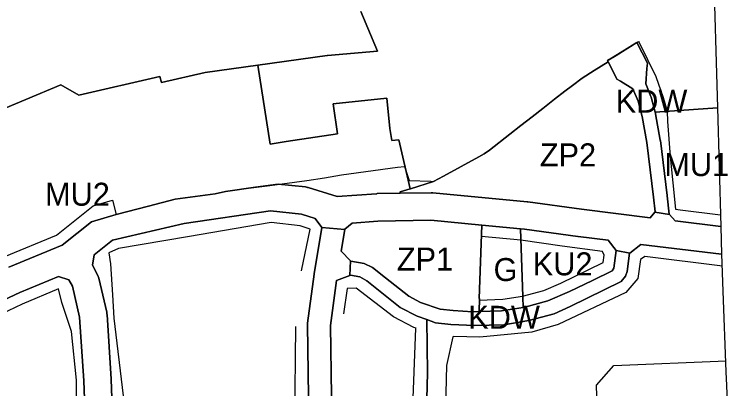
# Model space of a CAD drawing. Extents: x 7425930 to 7427318, y 5544765 to 5546387.
# Drawn here: x 7426835.8 to 7427147, y 5545888.3 to 5546051.3 of the extents above; entities that cross this region are included whole.
import ezdxf

# ---------------------------------------------------------------- set-up
doc = ezdxf.new("R2010")
doc.units = 0
for name, color, linetype in [('linie_rozgraniczajace', 7, 'Continuous'), ('linie_zabudowy_nieprzekraczalne', 7, 'Continuous'), ('oznaczenia_przeznaczen', 7, 'Continuous')]:
    doc.layers.add(name, color=color, linetype=linetype)

msp = doc.modelspace()

# ---------------------------------------------------------------- linework, layer by layer
at = {"layer": 'linie_rozgraniczajace'}
for points in [[(7427140.18, 5546075.21), (7427142.05, 5546010.56), (7427114.98, 5546008.71), (7427113.23, 5546015.19), (7427113.13, 5546015.48), (7427113.12, 5546015.54), (7427110.85, 5546021.1), (7427111.38, 5546027.77), (7427111.56, 5546030.07), (7427107.01, 5546038.98), (7427096.61, 5546032.62), (7427094.25, 5546031.18), (7427094.51, 5546030.67), (7427094.49, 5546030.68), (7427088.36, 5546026.88), (7427083.22, 5546023.55), (7427079.01, 5546020.35), (7427075.69, 5546017.81), (7427071.18, 5546014.31), (7427066.03, 5546010.32), (7427061.37, 5546006.7), (7427056.45, 5546002.89), (7427051.71, 5545999.17), (7427042.82, 5545992.23), (7427040.55, 5545990.61), (7427038.16, 5545989.19), (7427022.76, 5545980.8), (7427018.48, 5545978.47), (7427008.34, 5545975.33), (7427008.24, 5545975.37), (7427003.31, 5545996.73), (7427000.28, 5545996.34), (7426999.47, 5546001.6), (7426998.11, 5546014.82), (7426974.71, 5546012.35), (7426976.63, 5545999.33), (7426954.2, 5545995.96), (7426947.33, 5545994.79), (7426941.89, 5546029.19), (7426972.15, 5546033.4), (7426972.24, 5546033.33), (7426994.07, 5546035.21), (7426986.79, 5546052.49)], [(7426986.79, 5546052.49), (7426994.07, 5546035.21), (7426972.24, 5546033.33), (7426972.15, 5546033.4), (7426941.89, 5546029.19), (7426919.02, 5546026.02), (7426900, 5546021.67), (7426899.24, 5546024.29), (7426863.95, 5546016.1), (7426856.16, 5546020.62), (7426825.43, 5546007.85)], [(7426825.43, 5546007.85), (7426856.16, 5546020.62), (7426863.95, 5546016.1), (7426899.24, 5546024.29), (7426900, 5546021.67), (7426919.02, 5546026.02), (7426941.89, 5546029.19), (7426947.33, 5545994.79), (7426954.2, 5545995.96), (7426976.63, 5545999.33), (7426974.71, 5546012.35), (7426998.11, 5546014.82), (7426999.47, 5546001.6), (7427000.28, 5545996.34), (7427003.31, 5545996.73), (7427008.24, 5545975.37), (7427008.25, 5545975.32), (7427003.87, 5545974.01), (7427003.93, 5545973.41), (7426993.85, 5545973.23), (7426993.7, 5545973.19), (7426993.54, 5545973.21), (7426976.44, 5545972.02), (7426963.83, 5545975.91), (7426963.53, 5545975.95), (7426962.7, 5545976.14), (7426950.76, 5545977.41), (7426940.96, 5545976.11), (7426927.84, 5545974.14), (7426923.32, 5545973.18), (7426905.94, 5545970.85), (7426894.3, 5545967.8), (7426880.15, 5545964.12), (7426869.47, 5545960.98), (7426856.72, 5545950.85), (7426833.54, 5545941.2)], [(7426833.54, 5545941.2), (7426856.72, 5545950.85), (7426869.47, 5545960.98), (7426880.15, 5545964.12), (7426894.3, 5545967.8), (7426905.94, 5545970.85), (7426923.32, 5545973.18), (7426927.84, 5545974.14), (7426940.96, 5545976.11), (7426950.76, 5545977.41), (7426962.7, 5545976.14), (7426963.53, 5545975.95), (7426963.83, 5545975.91), (7426976.44, 5545972.02), (7426993.54, 5545973.21), (7426993.7, 5545973.19), (7426993.85, 5545973.23), (7427003.93, 5545973.41), (7427017.4, 5545973.65), (7427017.46, 5545973.65), (7427018.07, 5545973.63), (7427059.27, 5545969.74), (7427059.38, 5545969.72), (7427059.54, 5545969.71), (7427082.93, 5545966.43), (7427112.84, 5545962.74), (7427114.85, 5545965.17), (7427121.24, 5545964.14), (7427123.64, 5545961.4), (7427143.54, 5545958.95), (7427143.89, 5545946.81), (7427108.72, 5545951.16), (7427103.92, 5545947.35), (7427097.94, 5545948.41), (7427097.95, 5545948.51), (7427094.53, 5545952.91), (7427081.41, 5545954.53), (7427081.37, 5545954.54), (7427081.31, 5545954.54), (7427058.01, 5545957.81), (7427056.26, 5545957.97), (7427039.48, 5545959.56), (7427017.28, 5545961.65), (7426994.22, 5545961.23), (7426982.96, 5545960.45), (7426979.78, 5545957.8), (7426979.74, 5545957.6), (7426969.75, 5545958.56), (7426966.83, 5545962.43), (7426960.86, 5545964.27), (7426947.44, 5545965.69), (7426909.86, 5545960.25), (7426878.64, 5545952.93), (7426870.65, 5545946.59), (7426869.88, 5545942.05), (7426872.1, 5545937.95), (7426872.14, 5545937.78), (7426872.26, 5545937.62)], [(7426878.81, 5545872.44), (7426878.06, 5545892.28), (7426878.04, 5545892.36), (7426878.05, 5545892.43), (7426876.24, 5545920.67), (7426876.22, 5545920.76), (7426876.1, 5545921.64), (7426872.66, 5545936.46), (7426872.26, 5545937.62), (7426872.14, 5545937.78), (7426872.1, 5545937.95), (7426869.88, 5545942.05), (7426870.65, 5545946.59), (7426878.64, 5545952.93), (7426909.86, 5545960.25), (7426947.44, 5545965.69), (7426960.86, 5545964.27), (7426966.83, 5545962.43), (7426969.75, 5545958.56), (7426969.76, 5545958.55), (7426966.41, 5545938.27), (7426966.4, 5545938.18), (7426966.38, 5545938.11), (7426963.54, 5545916.81), (7426963.51, 5545916.15), (7426963.5, 5545916.08), (7426963.97, 5545884.9)], [(7426963.97, 5545884.9), (7426963.5, 5545916.08), (7426963.51, 5545916.15), (7426963.54, 5545916.81), (7426966.38, 5545938.11), (7426966.4, 5545938.18), (7426966.41, 5545938.27), (7426969.76, 5545958.55), (7426969.75, 5545958.56), (7426979.74, 5545957.6), (7426978.19, 5545948.25), (7426982.33, 5545943.95), (7426981.95, 5545937.55), (7426976.11, 5545935.38), (7426973.5, 5545915.86), (7426973.97, 5545885)], [(7427013.96, 5545822.16), (7427015.76, 5545895.24), (7427015.45, 5545918.38), (7427019.32, 5545917.02), (7427025.9, 5545916.29), (7427036.25, 5545915.79), (7427049.07, 5545916.17), (7427059.99, 5545917.94), (7427070.99, 5545920.9), (7427077.88, 5545924.1), (7427100.08, 5545934.93), (7427102.1, 5545937.26), (7427102.81, 5545939.27), (7427103.79, 5545947.25), (7427103.92, 5545947.35), (7427108.72, 5545951.16), (7427143.89, 5545946.81), (7427144.36, 5545930.79), (7427145.78, 5545895.67), (7427145.78, 5545895.64), (7427146.03, 5545889.65), (7427146.03, 5545889.57), (7427146.99, 5545865.9)], [(7426821.46, 5545922.33), (7426838.26, 5545930.17), (7426855.15, 5545937.2), (7426859.65, 5545935.74), (7426861.15, 5545932.96), (7426864.3, 5545919.41), (7426866.07, 5545891.75), (7426866.82, 5545871.96), (7426866.82, 5545871.93), (7426866.82, 5545871.9), (7426868.4, 5545838.29), (7426859.6, 5545808.92), (7426847.88, 5545776.09), (7426847.88, 5545776.07), (7426847.87, 5545776.06), (7426842.94, 5545761.99), (7426840.91, 5545750.25), (7426829.1, 5545718.41)], [(7426829.1, 5545718.41), (7426840.91, 5545750.25), (7426842.94, 5545761.99), (7426847.87, 5545776.06), (7426847.88, 5545776.07), (7426847.88, 5545776.09), (7426859.6, 5545808.92), (7426868.4, 5545838.29), (7426866.82, 5545871.9), (7426866.82, 5545871.93), (7426866.82, 5545871.96), (7426866.07, 5545891.75), (7426864.3, 5545919.41), (7426861.15, 5545932.96), (7426859.65, 5545935.74), (7426855.15, 5545937.2), (7426838.26, 5545930.17), (7426821.46, 5545922.33)], [(7426872.26, 5545937.62), (7426872.66, 5545936.46), (7426876.1, 5545921.64), (7426876.22, 5545920.76), (7426876.24, 5545920.67), (7426878.05, 5545892.43), (7426878.04, 5545892.36), (7426878.06, 5545892.28), (7426878.81, 5545872.44), (7426880.44, 5545837.83), (7426880.43, 5545837.81), (7426880.44, 5545837.79), (7426880.19, 5545835.83), (7426871.05, 5545805.33), (7426870.98, 5545805.21), (7426870.95, 5545805.04), (7426859.19, 5545772.07), (7426846.78, 5545736.72), (7426842.71, 5545722.38), (7426844.14, 5545718.64), (7426844.41, 5545718.61), (7426840.69, 5545708.83), (7426834.5, 5545706.76)], [(7426973.97, 5545885), (7426973.5, 5545915.86), (7426976.11, 5545935.38), (7426981.95, 5545937.55), (7426982.27, 5545937.67), (7426986.33, 5545937), (7426989.45, 5545935.27), (7427003.95, 5545923.68), (7427011.26, 5545919.87), (7427015.45, 5545918.38), (7427015.76, 5545895.24), (7427013.96, 5545822.16)]]:
    msp.add_lwpolyline(points, dxfattribs=at)
for points in [[(7427094.25, 5546031.18), (7427096.61, 5546032.62), (7427107.01, 5546038.98), (7427111.56, 5546030.07), (7427111.38, 5546027.77), (7427110.85, 5546021.1), (7427113.12, 5546015.54), (7427113.13, 5546015.48), (7427113.23, 5546015.19), (7427114.98, 5546008.71), (7427115.1, 5546008.25), (7427115.13, 5546008.1), (7427115.16, 5546007.99), (7427117.19, 5545996.45), (7427117.2, 5545996.34), (7427117.21, 5545996.31), (7427120.2, 5545972.37), (7427120.2, 5545972.32), (7427120.21, 5545972.32), (7427121.06, 5545964.33), (7427121.24, 5545964.14), (7427114.85, 5545965.17), (7427114.93, 5545965.27), (7427114.24, 5545971.65), (7427111.26, 5545995.49), (7427109.28, 5546006.82), (7427107.49, 5546013.45), (7427105.27, 5546018.91), (7427099.89, 5546022.14), (7427098.33, 5546023.08), (7427094.57, 5546030.55), (7427094.56, 5546030.56), (7427094.51, 5546030.67)], [(7427003.87, 5545974.01), (7427008.25, 5545975.32), (7427008.24, 5545975.37), (7427008.34, 5545975.33), (7427018.48, 5545978.47), (7427022.76, 5545980.8), (7427038.16, 5545989.19), (7427040.55, 5545990.61), (7427042.82, 5545992.23), (7427051.71, 5545999.17), (7427056.45, 5546002.89), (7427061.37, 5546006.7), (7427066.03, 5546010.32), (7427071.18, 5546014.31), (7427075.69, 5546017.81), (7427079.01, 5546020.35), (7427083.22, 5546023.55), (7427088.36, 5546026.88), (7427094.49, 5546030.68), (7427094.51, 5546030.67), (7427094.56, 5546030.56), (7427094.57, 5546030.55), (7427098.33, 5546023.08), (7427099.89, 5546022.14), (7427105.27, 5546018.91), (7427107.49, 5546013.45), (7427109.28, 5546006.82), (7427111.26, 5545995.49), (7427114.24, 5545971.65), (7427114.93, 5545965.27), (7427114.85, 5545965.17), (7427112.84, 5545962.74), (7427082.93, 5545966.43), (7427059.54, 5545969.71), (7427059.38, 5545969.72), (7427059.27, 5545969.74), (7427018.07, 5545973.63), (7427017.46, 5545973.65), (7427017.4, 5545973.65), (7427003.93, 5545973.41)], [(7427114.98, 5546008.71), (7427142.05, 5546010.56), (7427143.54, 5545958.95), (7427123.64, 5545961.4), (7427121.24, 5545964.14), (7427121.06, 5545964.33), (7427120.21, 5545972.32), (7427120.2, 5545972.32), (7427120.2, 5545972.37), (7427117.21, 5545996.31), (7427117.2, 5545996.34), (7427117.19, 5545996.45), (7427115.16, 5546007.99), (7427115.13, 5546008.1), (7427115.1, 5546008.25)], [(7426978.19, 5545948.25), (7426979.74, 5545957.6), (7426979.78, 5545957.8), (7426982.96, 5545960.45), (7426994.22, 5545961.23), (7427017.28, 5545961.65), (7427039.48, 5545959.56), (7427038.3, 5545927.58), (7427038.48, 5545927.58), (7427038.27, 5545921.86), (7427035.41, 5545921.78), (7427026.98, 5545922.3), (7427021.26, 5545922.86), (7427012.8, 5545925.82), (7427007.66, 5545928.53), (7426997.54, 5545936.59), (7426991.79, 5545941.12), (7426988.28, 5545942.83), (7426982.43, 5545943.85), (7426982.33, 5545943.95)], [(7427038.27, 5545921.86), (7427038.48, 5545927.58), (7427038.3, 5545927.58), (7427039.48, 5545959.56), (7427056.26, 5545957.97), (7427057.33, 5545928.45), (7427057.38, 5545928.36), (7427057.44, 5545923.64), (7427047.97, 5545922.15)], [(7427057.44, 5545923.64), (7427057.38, 5545928.36), (7427057.33, 5545928.45), (7427056.26, 5545957.97), (7427058.01, 5545957.81), (7427081.31, 5545954.54), (7427081.37, 5545954.54), (7427081.41, 5545954.53), (7427094.53, 5545952.91), (7427097.95, 5545948.51), (7427097.94, 5545948.41), (7427096.99, 5545940.83), (7427096.25, 5545939.6), (7427087.68, 5545935.42), (7427077.68, 5545930.64), (7427068.18, 5545926.55), (7427058.23, 5545923.76)], [(7426981.95, 5545937.55), (7426982.33, 5545943.95), (7426982.43, 5545943.85), (7426988.28, 5545942.83), (7426991.79, 5545941.12), (7426997.54, 5545936.59), (7427007.66, 5545928.53), (7427012.8, 5545925.82), (7427021.26, 5545922.86), (7427026.98, 5545922.3), (7427035.41, 5545921.78), (7427038.27, 5545921.86), (7427047.97, 5545922.15), (7427057.44, 5545923.64), (7427058.23, 5545923.76), (7427068.18, 5545926.55), (7427077.68, 5545930.64), (7427087.68, 5545935.42), (7427096.25, 5545939.6), (7427096.99, 5545940.83), (7427097.94, 5545948.41), (7427103.92, 5545947.35), (7427103.79, 5545947.25), (7427102.81, 5545939.27), (7427102.1, 5545937.26), (7427100.08, 5545934.93), (7427077.88, 5545924.1), (7427070.99, 5545920.9), (7427059.99, 5545917.94), (7427049.07, 5545916.17), (7427036.25, 5545915.79), (7427025.9, 5545916.29), (7427019.32, 5545917.02), (7427015.45, 5545918.38), (7427011.26, 5545919.87), (7427003.95, 5545923.68), (7426989.45, 5545935.27), (7426986.33, 5545937), (7426982.27, 5545937.67)]]:
    msp.add_lwpolyline(points, close=True, dxfattribs=at)
at = {"layer": 'linie_zabudowy_nieprzekraczalne'}
for points in [[(7427093.99, 5546031), (7427097.97, 5546033.45), (7427107.01, 5546038.98), (7427107.72, 5546039.47), (7427107.97, 5546038.98), (7427115.19, 5546024.18), (7427118.47, 5546015.04), (7427120.17, 5546009.15)], [(7427120.17, 5546009.15), (7427120.3, 5546004.65), (7427121.46, 5545989.41), (7427123.85, 5545966.46), (7427125.88, 5545966.23), (7427143.47, 5545963.95)], [(7426831.75, 5545945.87), (7426854.21, 5545955.19), (7426870.25, 5545967.89), (7426878.65, 5545970.35), (7426880.15, 5545964.12), (7426894.3, 5545967.8), (7426905.94, 5545970.85), (7426911.87, 5545971.64), (7426921.76, 5545972.97), (7426927.84, 5545974.14), (7426936.66, 5545975.46), (7426947.11, 5545976.82), (7426963.2, 5545978.96), (7426971, 5545980.08), (7426978.4, 5545981.4), (7427002.81, 5545984.8), (7427005.8, 5545985.05), (7427007.76, 5545978.96), (7427017.23, 5545978.69), (7427018.49, 5545978.57)], [(7426961, 5545939.59), (7426964.69, 5545957.73), (7426960.36, 5545959.23), (7426947.79, 5545960.64), (7426911.25, 5545954.37), (7426881.18, 5545949.42), (7426876.96, 5545947.49), (7426877.8, 5545942.67), (7426878.63, 5545929.13), (7426879.18, 5545918.95), (7426883.33, 5545885.21)], [(7427038.38, 5545926.8), (7427048.68, 5545927.35), (7427057.11, 5545928.61), (7427066.54, 5545931.12), (7427073.82, 5545934.32), (7427092.26, 5545943.28), (7427092.79, 5545946.48), (7427092.06, 5545948.04), (7427074.51, 5545950.43), (7427056.47, 5545952.94), (7427039.29, 5545954.54)], [(7427144.24, 5545941.61), (7427110.5, 5545945.84), (7427108.5, 5545944.62), (7427107.37, 5545936.22), (7427102.12, 5545930.24), (7427072.77, 5545916.21), (7427061.25, 5545912.96), (7427038.57, 5545910.72), (7427027.3, 5545911.05), (7427026.78, 5545910.9), (7427024.01, 5545898.38), (7427023.58, 5545880.23)], [(7426817.83, 5545714.78), (7426826.37, 5545723.84), (7426834.78, 5545751.26), (7426836.93, 5545759.67), (7426846.96, 5545785.83), (7426853.37, 5545806.21), (7426861.65, 5545834.56), (7426862.63, 5545841.81), (7426862.59, 5545856.37), (7426862.87, 5545892), (7426860.69, 5545913.21), (7426856.61, 5545925.78), (7426855.16, 5545931.8), (7426839.28, 5545925.06), (7426823.82, 5545917.81), (7426815.07, 5545911.63), (7426803.33, 5545903.3), (7426787.32, 5545894.35)], [(7427010.83, 5545914.62), (7427009.8, 5545914.98), (7427001, 5545919.65), (7426984.74, 5545932.1), (7426980.78, 5545931.94), (7426979.27, 5545920.91)], [(7426958.04, 5545873.88), (7426958.47, 5545915.39)], [(7427009.21, 5545876.69), (7427010.74, 5545914.62)], [(7427090.12, 5545865.48), (7427089.4, 5545889.81), (7427096.99, 5545898.46), (7427145.89, 5545900.44)]]:
    msp.add_lwpolyline(points, dxfattribs=at)

# ---------------------------------------------------------------- texts
at = {"layer": 'oznaczenia_przeznaczen'}
for s, p in [('KDW', (7427097.79, 5546008.49)), ('ZP2', (7427064.71, 5545985.12)), ('MU1', (7427118.96, 5545980.88)), ('MU2', (7426849.23, 5545967.98)), ('ZP1', (7427002.46, 5545939.74)), ('KU2', (7427061.65, 5545937.66)), ('G', (7427044.58, 5545935.18)), ('KDW', (7427033.56, 5545914.4))]:
    msp.add_text(s, height=10, dxfattribs=at).set_placement(p)

doc.saveas('drawing.dxf')
